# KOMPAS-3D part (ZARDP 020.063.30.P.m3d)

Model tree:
1. Плоскость XY
2. Плоскость ZX
3. Плоскость ZY
4. Ось X
5. Ось Y
6. Ось Z
7. Начало координат
8. Смещенная плоскость:2
     Расстояние = 60
9. Смещенная плоскость:3
     Расстояние = 102
10. Смещенная плоскость:4
     Расстояние = 102
11. Булева операция:1
12. Булева операция:2
13. Булева операция:3
14. Булева операция:4
15. Булева операция:5
16. Булева операция:6
